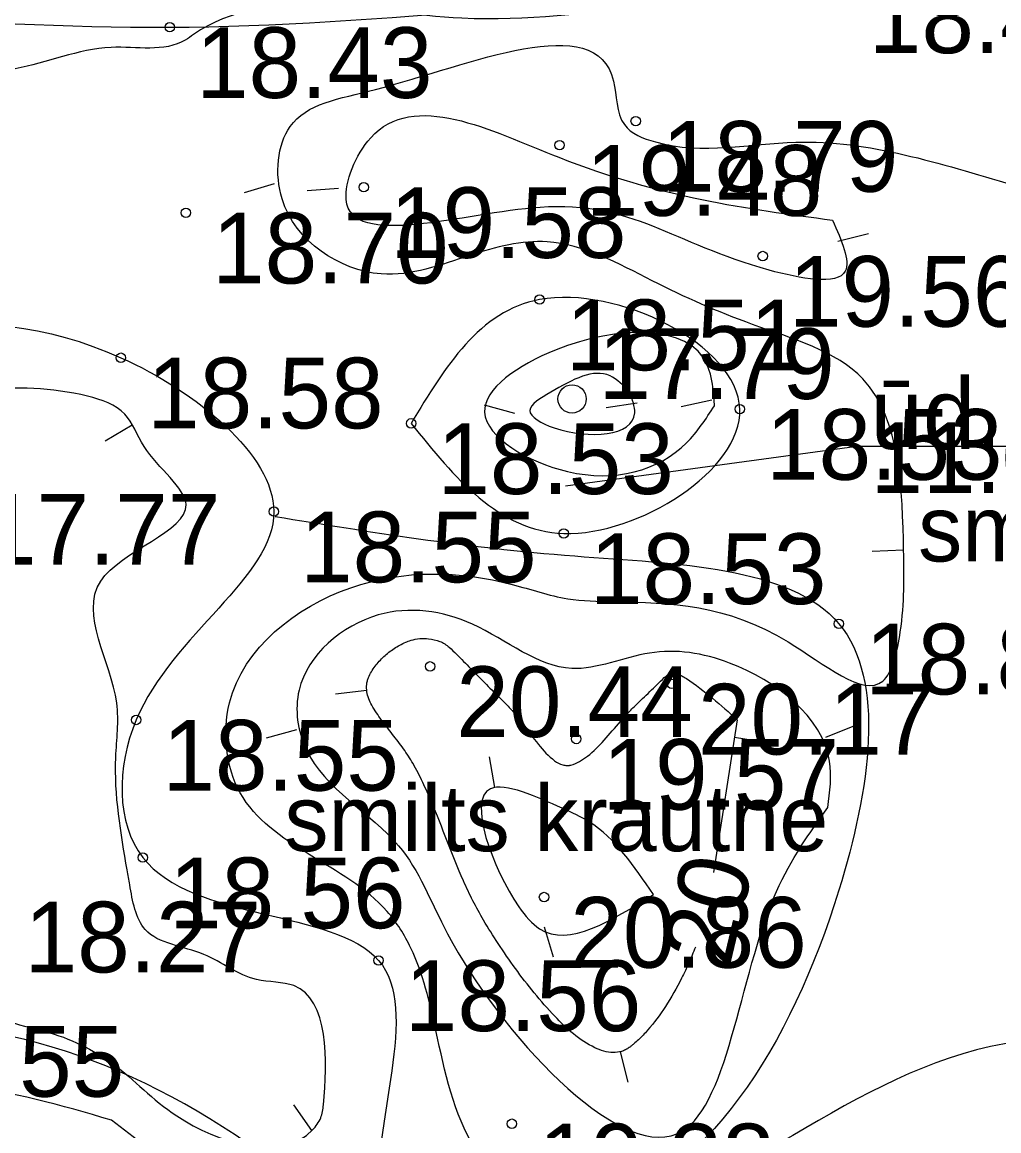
# Model space of a CAD drawing. Extents: x 521824 to 524158, y 294774 to 296228.
# Drawn here: x 522103.82 to 522119.37, y 295991.14 to 296008.78 of the extents above; entities that cross this region are included whole.
import ezdxf

# ---------------------------------------------------------------- set-up
doc = ezdxf.new("R2010")
doc.units = 0
for name, color, linetype in [('HIDG_AATZ_####_TKST_#', 7, 'Continuous'), ('HIDG_ELEM_####_####_#', 7, 'Continuous'), ('HIDG_GRAV_####_####_#', 7, 'Continuous'), ('HIDG_HORZ_PAMT_####_#', 7, 'Continuous'), ('HIDG_HORZ_RESN_####_#', 7, 'Continuous'), ('HIDG_PLIN_####_####_#', 7, 'Continuous'), ('HIDG_UATZ_####_TKST_#', 7, 'Continuous'), ('RELJ_AATZ_####_TKST_#', 7, 'Continuous'), ('RELJ_ELEM_####_####_#', 7, 'Continuous'), ('RELJ_HORZ_####_TKST_#', 7, 'Continuous'), ('RELJ_HORZ_PAMT_####_#', 7, 'Continuous'), ('RELJ_HORZ_RESN_####_#', 7, 'Continuous'), ('TERT_IZMT_####_TKST_#', 7, 'Continuous'), ('TERT_KONT_####_####_#', 7, 'Continuous')]:
    doc.layers.add(name, color=color, linetype=linetype)

msp = doc.modelspace()

# ---------------------------------------------------------------- linework, layer by layer
at = {"layer": 'HIDG_ELEM_####_####_#'}
msp.add_circle((522112.578, 296002.786), 0.225, dxfattribs=at)
at = {"layer": 'HIDG_GRAV_####_####_#'}
msp.add_spline([(522091.121, 296012.976), (522092.677, 296011.868), (522092.434, 296009), (522095.282, 296008.691), (522106.173, 296008.702), (522116.886, 296009.415), (522127.197, 296009.97), (522145.108, 296014.247), (522158.761, 296014.777), (522175.265, 296015.722), (522181.257, 296017.136), (522181.909, 296017.173), (522183.274, 296011.283)], degree=3, dxfattribs=at)
at = {"layer": 'HIDG_HORZ_PAMT_####_#'}
for p, q in [((522114.313, 296002.667), (522114.802, 296002.773)), ((522111.668, 296002.554), (522111.186, 296002.686)), ((522105.142, 296002.122), (522105.574, 296002.373)), ((522108.141, 295991.549), (522108.432, 295991.143))]:
    msp.add_line(p, q, dxfattribs=at)
for points in [[(522097.456, 296003.003), (522098.42, 296003.112), (522098.886, 296003.109), (522101.493, 296002.854), (522104.863, 296002.829), (522105.455, 296002.546), (522105.764, 296002.03), (522106.434, 296001.103), (522105.073, 295999.884), (522105.328, 295997.947), (522105.313, 295997.082), (522105.495, 295995.289), (522105.536, 295995.052), (522105.782, 295994.342), (522106.713, 295993.946), (522107.552, 295993.546), (522108.149, 295993.448), (522108.619, 295991.553), (522108.577, 295991.344), (522108.448, 295991.154), (522106.283, 295991.375), (522105.272, 295992.2), (522104.189, 295992.719), (522103.543, 295992.913), (522103.242, 295993.07), (522101.964, 295993.08), (522101.329, 295993.113), (522100.932, 295993.02), (522099.761, 295992.856), (522098.335, 295992.439), (522097.436, 295991.876), (522096.287, 295991.458), (522094.937, 295990.58), (522094.192, 295990.336), (522093.424, 295990.187), (522091.553, 295990.123), (522089.682, 295990.202), (522089.358, 295990.216), (522085.744, 295990.713), (522081.631, 295990.342), (522080.807, 295990.11), (522079.09, 295989.003), (522078.197, 295988.522), (522077.728, 295988.334), (522077.237, 295988.193), (522076.001, 295988.101), (522074.761, 295988.259), (522072.524, 295989.01), (522071.862, 295989.025), (522071.249, 295988.887), (522068.367, 295988.362), (522067.498, 295988.56), (522067.064, 295988.714), (522066.631, 295988.911), (522064.566, 295990.452), (522063.244, 295992.536), (522063.001, 295993.19), (522062.602, 295994.158), (522059.484, 295999.35), (522058.893, 296002.168), (522061.43, 296003.805), (522064.048, 296003.805), (522069.557, 296001.404), (522072.32, 296003.741), (522074.302, 296004.815), (522097.456, 296003.003)], [(522114.845, 296002.677), (522114.402, 296002.088), (522112.506, 296001.631), (522111.186, 296002.575), (522112.323, 296003.567), (522114.731, 296003.327), (522114.845, 296002.677)]]:
    msp.add_spline(points, degree=3, dxfattribs=at)
at = {"layer": 'HIDG_HORZ_RESN_####_#'}
msp.add_line((522113.12, 296002.648), (522113.614, 296002.724), dxfattribs=at)
msp.add_spline([(522113.499, 296002.895), (522113.575, 296002.563), (522112.291, 296002.328), (522111.906, 296002.604), (522112.238, 296002.893), (522113.183, 296003.153), (522113.499, 296002.895)], degree=3, dxfattribs=at)
at = {"layer": 'HIDG_PLIN_####_####_#'}
for points in [[(522077.435, 296005.57), (522085.461, 296004.306), (522098.512, 296003.392), (522105.395, 296003.443), (522107.83, 296000.993), (522105.638, 295997.677), (522105.744, 295995.487), (522109.498, 295993.85), (522109.498, 295989.848), (522114.208, 295986.087), (522123.878, 295989.299), (522133.271, 295980.049), (522137.318, 295976.793), (522131.563, 295972.766), (522130.654, 295969.62), (522124.01, 295968.477), (522115.857, 295969.771), (522111.112, 295969.734), (522110.471, 295975.549), (522112.358, 295978.857), (522112.409, 295984.266), (522101.265, 295992.806), (522096.41, 295991.057), (522092.914, 295989.062)], [(522110.015, 296002.398), (522112.062, 296004.368), (522115.249, 296002.625), (522112.445, 296000.646), (522110.015, 296002.398)]]:
    msp.add_spline(points, degree=3, dxfattribs=at)
at = {"layer": 'HIDG_UATZ_####_TKST_#'}
msp.add_lwpolyline([(522112.472, 296001.402), (522117.11, 296002.037), (522123.076, 296002.037)], dxfattribs=at)
at = {"layer": 'RELJ_ELEM_####_####_#'}
for centre in [(522106.173, 296008.702), (522113.591, 296007.209), (522112.38, 296006.826), (522109.261, 296006.156), (522106.429, 296005.749), (522115.613, 296005.061), (522112.062, 296004.368), (522105.395, 296003.443), (522115.249, 296002.625), (522110.015, 296002.398), (522107.83, 296000.993), (522112.445, 296000.646), (522116.826, 295999.208), (522110.317, 295998.53), (522114.165, 295998.252), (522105.638, 295997.677), (522112.645, 295997.374), (522105.744, 295995.487), (522112.132, 295994.859), (522109.498, 295993.85), (522111.62, 295991.251)]:
    msp.add_circle(centre, 0.075, dxfattribs=at)
at = {"layer": 'RELJ_HORZ_PAMT_####_#'}
for p, q in [((522107.361, 296006.074), (522107.842, 296006.213)), ((522108.358, 296006.106), (522108.857, 296006.14)), ((522117.296, 296005.412), (522116.811, 296005.293)), ((522117.357, 296000.363), (522117.857, 296000.384)), ((522107.713, 295997.391), (522108.195, 295997.526)), ((522117.075, 295997.584), (522116.611, 295997.397)), ((522111.258, 295997.092), (522111.344, 295996.6)), ((522112.283, 295993.899), (522112.139, 295994.378))]:
    msp.add_line(p, q, dxfattribs=at)
for points in [[(522148.922, 295987.907), (522148.552, 295987.672), (522148.13, 295987.547), (522142.145, 295984.715), (522140.627, 295984.14), (522138.684, 295984.539), (522138.079, 295984.82), (522136.131, 295985.03), (522135.49, 295984.543), (522137.464, 295983.3), (522138.906, 295981.587), (522137.92, 295981.159), (522136.668, 295979.841), (522134.454, 295979.765), (522132.917, 295981.68), (522132.347, 295981.94), (522130.67, 295983.065), (522129.163, 295984.385), (522127.535, 295986.166), (522125.611, 295988.145), (522124.556, 295989.313), (522123.674, 295991.099), (522122.931, 295991.88), (522120.148, 295992.607), (522113.348, 295989.576), (522112.896, 295989.445), (522112.055, 295989.829), (522111.032, 295990.862), (522110.41, 295992.733), (522110.011, 295994.047), (522109.634, 295994.629), (522107.294, 295996.519), (522107.125, 295997.948), (522109.054, 295999.781), (522111.627, 295999.833), (522112.509, 295999.607), (522113.225, 295999.56), (522116.018, 295998.918), (522117.525, 295998.295), (522117.804, 295999.078), (522117.857, 296000.377), (522117.21, 296003.104), (522115.45, 296003.973), (522113.854, 296004.668), (522112.181, 296005.288), (522110.957, 296005.073), (522109.538, 296004.776), (522107.962, 296005.969), (522108.089, 296007.122), (522109.448, 296007.712), (522113.238, 296007.845), (522113.411, 296007.152), (522113.904, 296006.876), (522116.143, 296006.873), (522119.594, 296006.195), (522119.864, 296006.152), (522119.969, 296006.174), (522125.143, 296008.842), (522127.842, 296009.01), (522129.451, 296008.699), (522130.726, 296008.377), (522130.898, 296008.393), (522131.43, 296008.639), (522134.341, 296010.531), (522136.866, 296011.095), (522140.038, 296011.621), (522143.287, 296012.722), (522147.223, 296013.232), (522147.912, 296013.352), (522151.159, 296013.727), (522152.637, 296013.188), (522160.473, 296010.584), (522163.167, 296012.474), (522166.885, 296013.245), (522174.018, 296014.184), (522179.448, 296015.31), (522180.074, 296015.597), (522181.317, 296015.467), (522181.799, 296014.868), (522182.175, 296012.697), (522181.883, 296011.954), (522177.242, 296010.373), (522176.264, 296009.891), (522175.768, 296009.558), (522172.684, 296008.401), (522168.721, 296007.952), (522167.696, 296007.902), (522160.834, 296005.775), (522159.869, 296005.009), (522158.414, 295999.127), (522158.015, 295997.98), (522157.507, 295997.03)], [(522147.001, 296013.879), (522145.334, 296014.111), (522144.908, 296014.079), (522138.003, 296012.088), (522137.814, 296012.008), (522135.146, 296011.271), (522131.635, 296010.287), (522130.341, 296009.639), (522127.864, 296009.75), (522127.714, 296009.761), (522127.564, 296009.8), (522127.264, 296009.832), (522127.105, 296009.79), (522126.615, 296009.677), (522125.425, 296009.552), (522124.235, 296009.457), (522121.853, 296009.334), (522117.084, 296009.201), (522116.821, 296009.194), (522115.322, 296009.109), (522113.823, 296009.021), (522110.825, 296008.845), (522106.552, 296008.587), (522106.42, 296008.498), (522105.24, 296008.381), (522103.71, 296008.042), (522102.575, 296008.01), (522101.436, 296008.101), (522100.295, 296008.227), (522099.156, 296008.295), (522097.506, 296008.302), (522096.685, 296008.185), (522096.274, 296008.062), (522096.069, 296007.981), (522095.864, 296007.884), (522092.757, 296008.408), (522089.948, 296009.718), (522091.502, 296010.619), (522091.012, 296011.544), (522089.457, 296012.256), (522087.875, 296012.556), (522086.266, 296013.266), (522086.078, 296014.194)], [(522116.727, 296005.633), (522112.368, 296006.632), (522109.372, 296006.942), (522108.982, 296005.96), (522112.068, 296005.835), (522115.714, 296004.837), (522116.927, 296004.82), (522116.727, 296005.633)], [(522116.651, 295996.284), (522115.833, 295994.947), (522114.246, 295991.089), (522110.597, 295994.271), (522109.817, 295995.674), (522108.341, 295997.215), (522108.231, 295998.15), (522109.491, 295999.348), (522110.991, 295999.2), (522112.576, 295998.495), (522113.813, 295998.742), (522115.085, 295998.583), (522116.678, 295997.02), (522116.651, 295996.284)], [(522113.873, 295994.899), (522112.06, 295994.354), (522111.73, 295994.705), (522111.279, 295996.583), (522112.42, 295996.271), (522112.849, 295996.056), (522113.873, 295994.899)], [(522105.243, 295991.309), (522107.125, 295989.481), (522105.442, 295982.655), (522105.328, 295982.465), (522105.046, 295982.174), (522100.647, 295978.292), (522099.723, 295978.542), (522098.381, 295979.861), (522097.478, 295981.162), (522096.717, 295982.97), (522095.071, 295985.77), (522096.114, 295987.775), (522096.694, 295990.056), (522100.17, 295991.49), (522101.306, 295991.791), (522102.823, 295991.848), (522105.243, 295991.309)]]:
    msp.add_spline(points, degree=3, dxfattribs=at)
at = {"layer": 'RELJ_HORZ_RESN_####_#'}
for p, q in [((522108.813, 295998.095), (522109.31, 295998.149)), ((522115.207, 295997.68), (522114.829, 295995.248)), ((522115.657, 295997.319), (522115.163, 295997.396)), ((522113.472, 295991.912), (522113.347, 295992.396))]:
    msp.add_line(p, q, dxfattribs=at)
msp.add_spline([(522114.541, 295994.06), (522114.438, 295993.81), (522114.323, 295993.567), (522114.064, 295993.116), (522113.78, 295992.738), (522113.634, 295992.586), (522113.561, 295992.521), (522113.524, 295992.491), (522113.488, 295992.463), (522113.428, 295992.427), (522113.366, 295992.402), (522113.233, 295992.383), (522112.942, 295992.46), (522112.303, 295992.962), (522111.676, 295993.722), (522111.401, 295994.12), (522111.169, 295994.49), (522110.999, 295994.8), (522110.849, 295995.115), (522110.589, 295995.75), (522110.338, 295996.378), (522110.2, 295996.684), (522110.046, 295996.982), (522109.893, 295997.218), (522109.72, 295997.447), (522109.546, 295997.675), (522109.389, 295997.912), (522109.341, 295998.015), (522109.312, 295998.127), (522109.309, 295998.242), (522109.319, 295998.298), (522109.337, 295998.351), (522109.442, 295998.531), (522109.581, 295998.686), (522109.746, 295998.814), (522109.836, 295998.868), (522109.929, 295998.914), (522110.014, 295998.945), (522110.293, 295998.97), (522110.472, 295998.927), (522110.552, 295998.887), (522110.622, 295998.833), (522110.851, 295998.61), (522111.075, 295998.383), (522111.299, 295998.155), (522111.527, 295997.929), (522111.656, 295997.789), (522111.785, 295997.626), (522112.043, 295997.288), (522112.301, 295997.028), (522112.431, 295996.962), (522112.495, 295996.952), (522112.528, 295996.953), (522112.544, 295996.955), (522112.552, 295996.956), (522112.56, 295996.958), (522112.823, 295997.1), (522113.087, 295997.354), (522113.35, 295997.654), (522113.482, 295997.801), (522113.548, 295997.869), (522113.614, 295997.934), (522113.73, 295998.045), (522113.845, 295998.156), (522113.959, 295998.267), (522114.076, 295998.376), (522114.109, 295998.398), (522114.235, 295998.409), (522114.324, 295998.381), (522114.399, 295998.336), (522115.207, 295997.68)], degree=3, dxfattribs=at)
at = {"layer": 'TERT_KONT_####_####_#'}
msp.add_spline([(522107.853, 296000.916), (522112.621, 296000.287), (522116.826, 295999.208), (522116.826, 295994.966), (522112.748, 295989.824), (522109.498, 295989.848)], degree=3, dxfattribs=at)

# ---------------------------------------------------------------- texts
at = {"layer": 'HIDG_AATZ_####_TKST_#'}
for s, p in [(' 17.79', (522112.578, 296002.786)), (' 17.77', (522102.796, 296000.151)), (' 18.27', (522103.444, 295993.659))]:
    msp.add_text(s, height=1.125, dxfattribs=at).set_placement(p)
at = {"layer": 'HIDG_UATZ_####_TKST_#'}
for s, p in [('ūd.līm. 18.52', (522117.328, 296001.991)), ('11.05.20', (522117.328, 296001.287))]:
    msp.add_text(s, height=1.125, dxfattribs=at).set_placement(p)
at = {"layer": 'RELJ_AATZ_####_TKST_#'}
for s, p in [(' 18.46', (522116.886, 296008.29)), (' 18.43', (522106.173, 296007.577)), (' 18.79', (522113.591, 296006.084)), (' 19.48', (522112.38, 296005.701)), (' 19.58', (522109.261, 296005.031)), (' 18.70', (522106.429, 296004.624)), (' 19.56', (522115.613, 296003.936)), (' 18.51', (522112.062, 296003.243)), (' 18.58', (522105.395, 296002.318)), (' 18.53', (522115.249, 296001.5)), (' 18.53', (522110.015, 296001.273)), (' 18.55', (522107.83, 295999.868)), (' 18.53', (522112.445, 295999.521)), (' 18.85', (522116.826, 295998.083)), (' 20.44', (522110.317, 295997.405)), (' 20.17', (522114.165, 295997.127)), (' 18.55', (522105.638, 295996.552)), (' 19.57', (522112.645, 295996.249)), (' 18.56', (522105.744, 295994.362)), (' 20.86', (522112.132, 295993.734)), (' 18.56', (522109.498, 295992.725)), (' 18.55', (522101.265, 295991.681)), (' 19.38', (522111.62, 295990.126))]:
    msp.add_text(s, height=1.125, dxfattribs=at).set_placement(p)
at = {"layer": 'RELJ_HORZ_####_TKST_#'}
msp.add_text('20', height=1.125, rotation=76.6239, dxfattribs=at).set_placement((522115.083, 295993.724))
at = {"layer": 'TERT_IZMT_####_TKST_#'}
for s, p in [('smilts', (522118.088, 296000.2)), ('smilts krautne', (522107.998, 295995.589))]:
    msp.add_text(s, height=1.05, dxfattribs=at).set_placement(p)

doc.saveas('drawing.dxf')
